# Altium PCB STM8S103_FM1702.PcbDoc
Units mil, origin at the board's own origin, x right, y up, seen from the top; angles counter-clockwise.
Board outline 2660.03 x 1670.03 mil, 2 copper layers (Top Layer, Bottom Layer); 63 components, 54 nets, 258 pads, 49 vias.
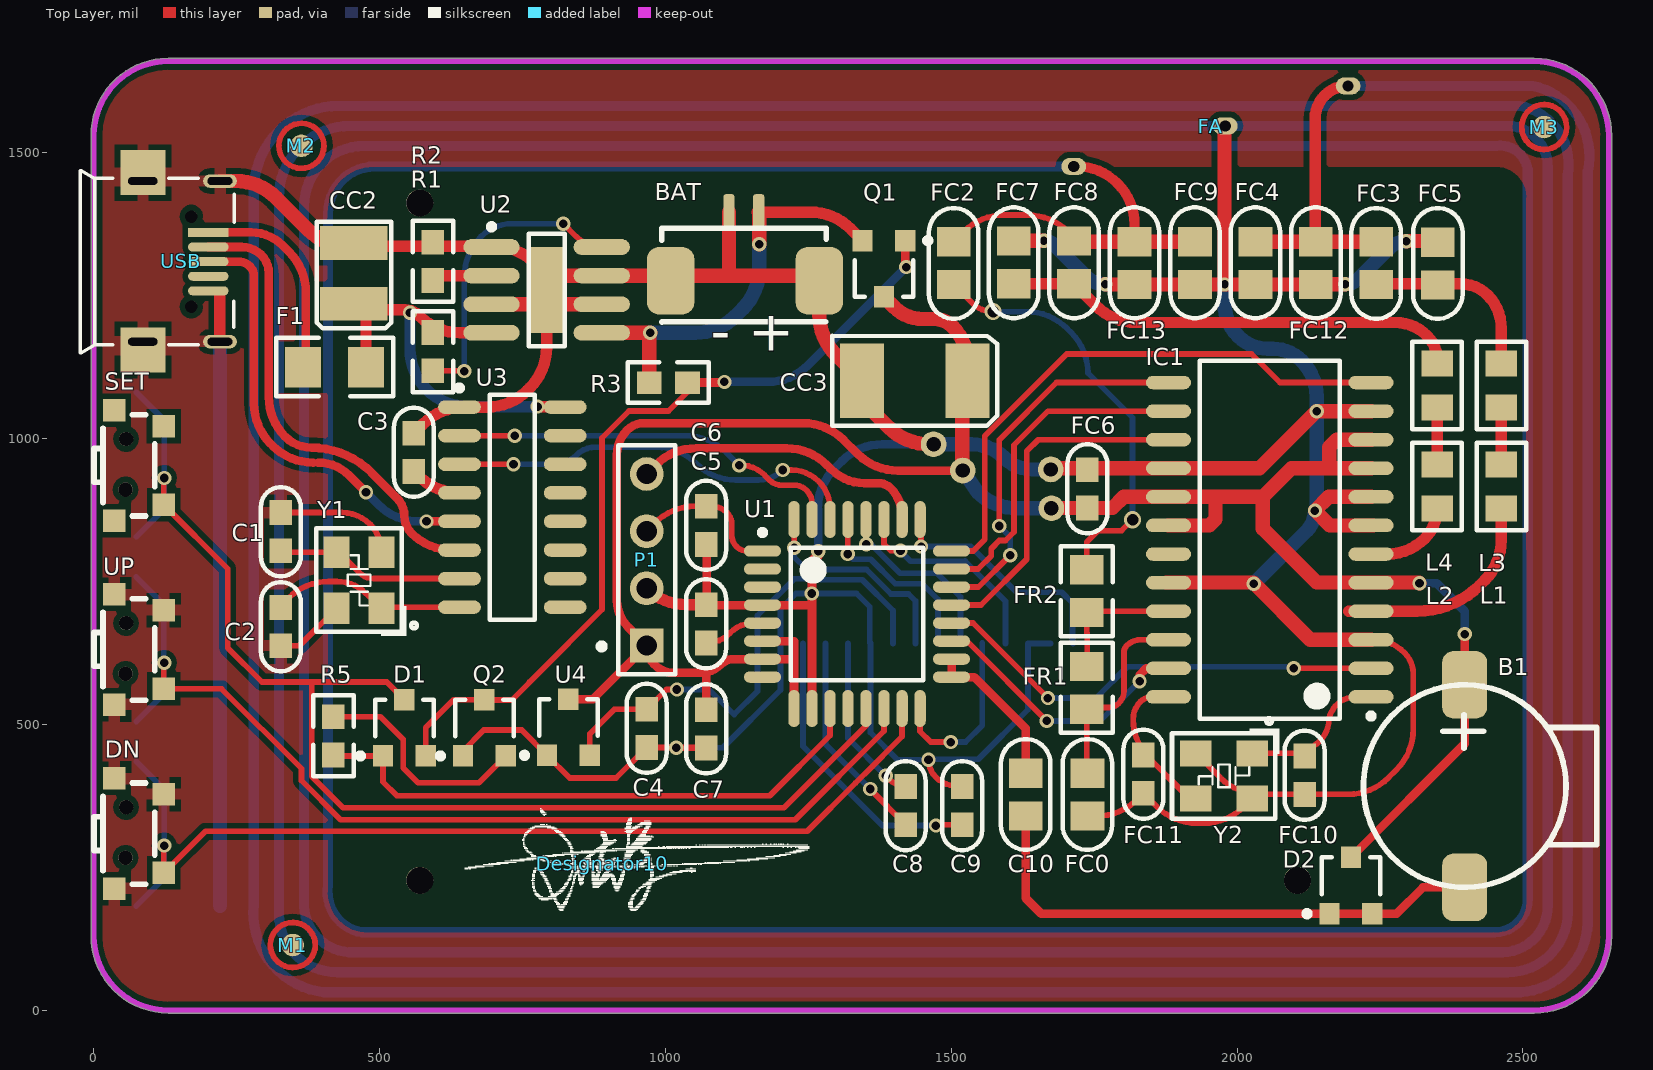
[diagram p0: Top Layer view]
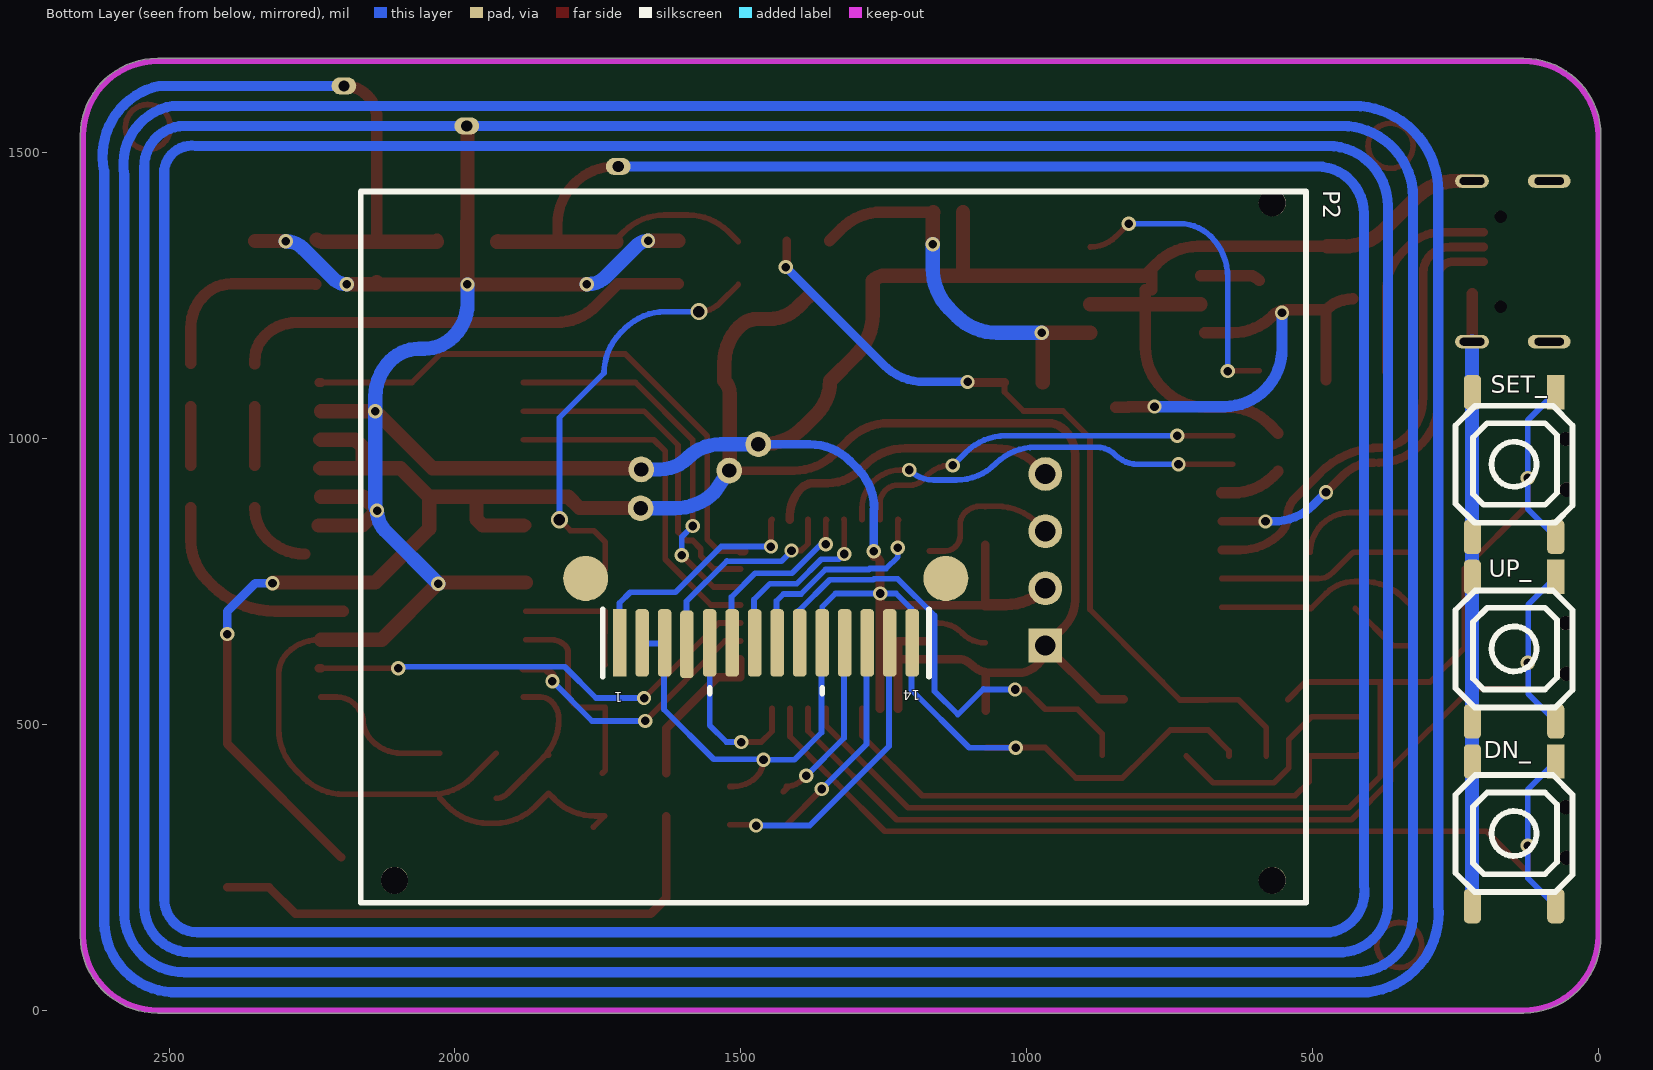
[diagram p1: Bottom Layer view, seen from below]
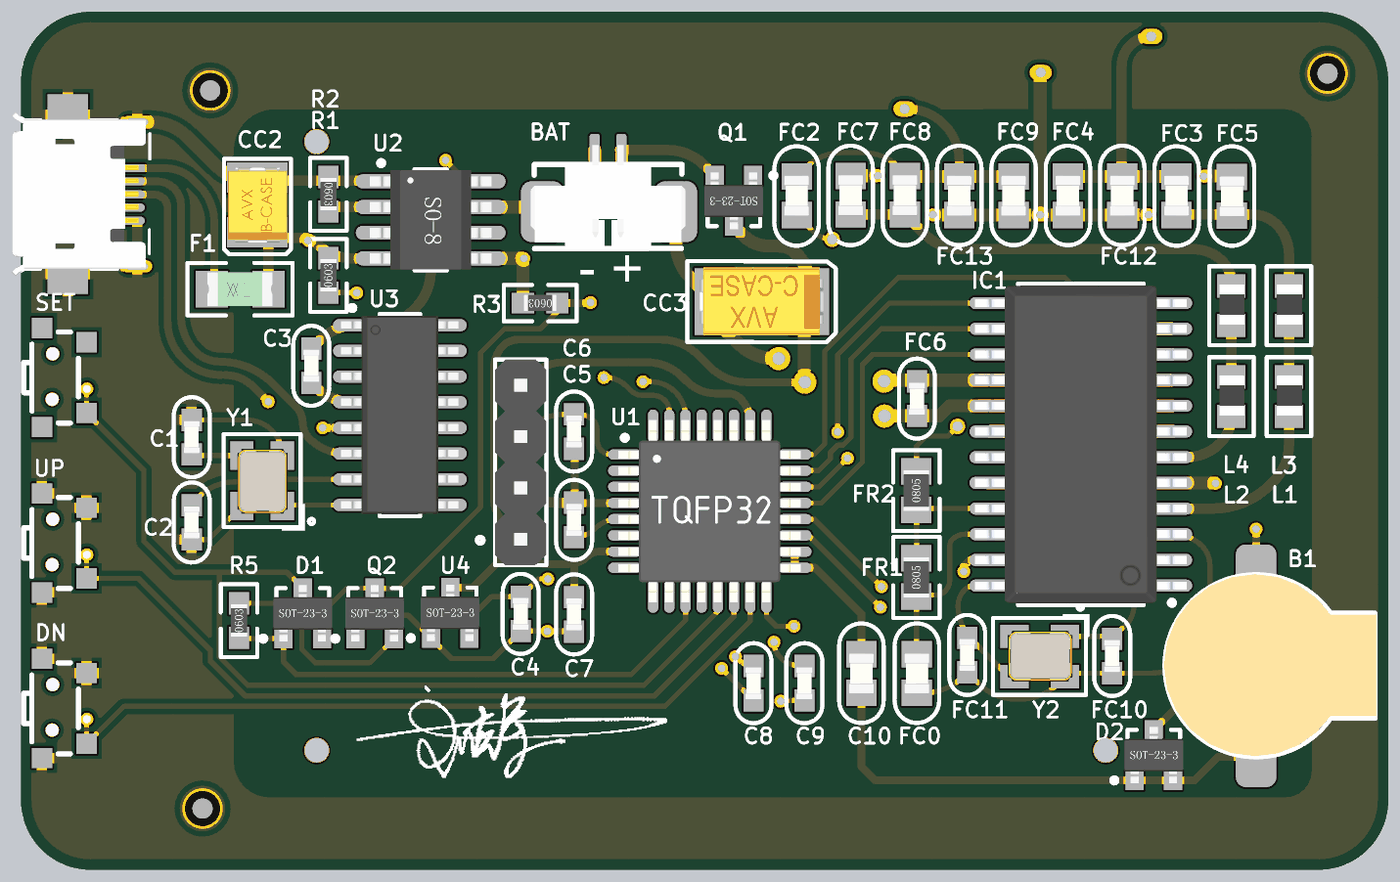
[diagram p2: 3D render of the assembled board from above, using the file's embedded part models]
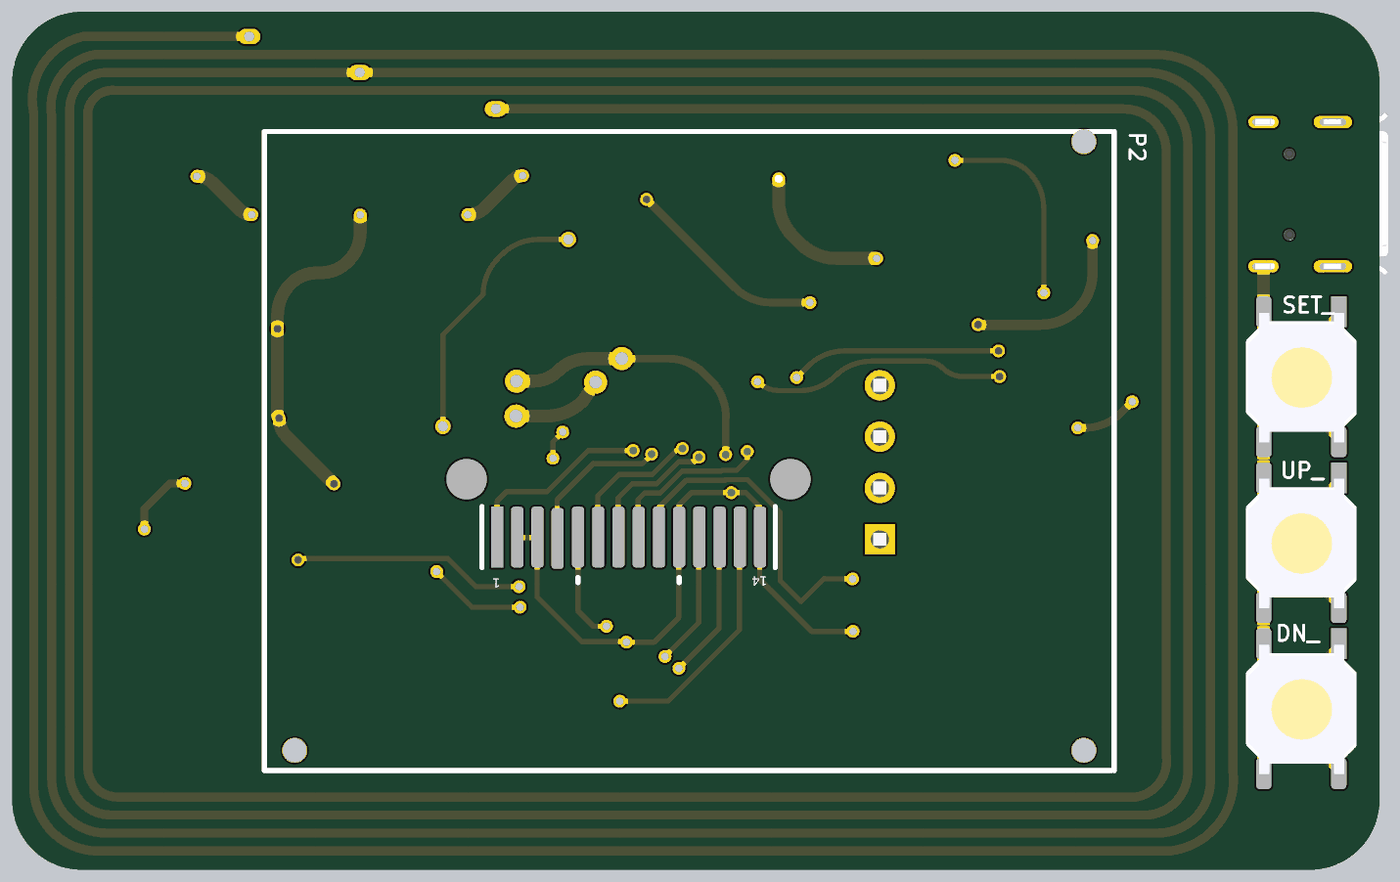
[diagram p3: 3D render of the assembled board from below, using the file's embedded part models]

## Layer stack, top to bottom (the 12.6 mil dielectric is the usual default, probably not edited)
Top Solder: solder mask 0.4, Solder Resist, Dk 3.5
Top Layer: signal copper 1.4
Dielectric1: dielectric 12.6, FR-4, Dk 4.8
Bottom Layer: signal copper 1.4
Bottom Solder: solder mask 0.4, Solder Resist, Dk 3.5

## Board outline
-4.45,117.69 cw(c0,120) -5.02,120 -5.02,1530 cw(c130,1530) 130,1665.02 2520,1665.02 cw(c2520,1530) 2655.02,1530 2655.02,130 cw(c2520,130) 2520,-5.01 130,-5.01 cw(c130,130)

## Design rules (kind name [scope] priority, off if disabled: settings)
Clearance poly [inpolygon] p1: gap=10
Clearance [All] p2: gap=8
ComponentClearance [All] p1: gap=0 collisioncheckmode=3 verticalgap=0 showdistances=FALSE
FabricationTestPointUsage TestPointUsage [All] p1: valid=0 allowmultiple=FALSE
FabricationTestpoint Testpoint [All] p1: side=3 testpointundercomponent=TRUE minsize=40 maxsize=100 preferedsize=60 minholesize=0 maxholesize=40 preferedholesize=32 testpointgrid=1 allowsidetop=TRUE allowsidebottom=TRUE usegrid=TRUE gridtolerance=0.01
HoleSize [All] p1: absolutevalues=TRUE maxlimit=150 minlimit=10 maxpercent=80.000 minpercent=20.000
PolygonConnect [All] p1: connectstyle=Relief reliefconductorwidth=20 reliefentries=4 polygonreliefangle="90 Angle" airgapwidth=10
RoutingVias [All] p1: holewidth=28 width=50 viastyle="Through Hole" minholewidth=28 minwidth=50 maxholewidth=28 maxwidth=50
SilkToSilkClearance [All] p1: silktosilkclearance=0
SolderMaskExpansion [All] p1: expansion=4
UnpouredPolygon [All] p1: allowunpoured=FALSE
Width [All] p1: maxlimit=50 minlimit=10 preferedwidth=20 bottomlayer_prefwidth=10 minimp=50.000000 maximp=50.000000 favimp=50.000000
24 further rules are at their usual default settings.

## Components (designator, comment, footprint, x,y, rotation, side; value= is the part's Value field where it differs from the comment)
B1 "BUZZER" BUZZ_9025 2398,392 r90 top
BAT "Battery" HX1.25-2 1289,1405 r180 top
C1 "C0603" C0603 327,837 r90 top
C2 "C0603" C0603 327,671 r270 top
C3 "C0603" C0603 559.57,976 r270 top
C4 "C0603" C0603 967,493 r270 top
C5 "C0603" C0603 1071,676 r90 top
C6 "C0603" C0603 1071,848 r270 top
C7 "C0603" C0603 1071,492 r270 top
C8 "C0603" C0603 1420,358 r90 top
C9 "C0603" C0603 1519,358 r90 top
C10 "C0805" C0805 1630,377 r90 top
CC2 "Cap Tan B" TAN-B-3528 455,1289 r270 top
CC3 "Cap Tan C" TAN-C-6032 1436,1101 r0 top
D1 "BAS40_5" SOT-23 543,494 r0 top
D2 "BAS40_5" SOT-23 2199,218 r0 top
Designator10 "Comment" LOGO 889,257 r0 top
DN "Button" BUTTON_SMD 79,309 r90 top
DN_ "Button" SWITCH_SMD 147,309 r270 bottom
F1 "300mA" F1206 421,1125 r0 top
FA "FM1702_Antenna" FM1702_ANTENNA 1834,1436 r180 top locked
FC0 "C0805" C0805 1738,377 r90 top
FC2 "C0805" C0805 1504,1307 r270 top
FC3 "C0805" C0805 2243.29,1307 r270 top
FC4 "C0805" C0805 2031.86,1307 r90 top
FC5 "C0805" C0805 2351,1306 r90 top
FC6 "C0603" C0603 1738,912 r90 top
FC7 "C0805" C0805 1609,1308 r270 top
FC8 "C0805" C0805 1714.71,1308 r270 top
FC9 "C0805" C0805 1926.14,1307 r90 top
FC10 "C0603" C0603 2118,411 r270 top
FC11 "C0603" C0603 1836,413 r270 top
FC12 "C0805" C0805 2137.57,1307 r90 top
FC13 "C0805" C0805 1820.43,1307 r90 top
FR1 "?" R0805 1737,564 r90 top
FR2 "?" R0805 1737,733 r90 top
IC1 "FM1702" SOP-24L 2057,823 r180 top
L1 "Inductor Chip" L2013-0805 2462,916 r90 top
L2 "Inductor Chip" L2013-0805 2350,916 r90 top
L3 "Inductor Chip" L2013-0805 2462,1093 r90 top
L4 "Inductor Chip" L2013-0805 2350,1093 r90 top
M1 "Mark" MARK 348,114 r180 top
M2 "Mark" MARK 363,1512 r180 top
M3 "Mark" MARK 2537,1545 r180 top
P1 "Header 4" HDR1X4 967,638 r90 top
P2 "SOG_12864" SOG12864 511,1432 r0 bottom
Q1 "IRLML6401" SOT-23 1382,1297 r180 top
Q2 "NPN-SMT" SO-G3/C2.5 683,494 r0 top
R1 "?" R0603 593,1152 r90 top
R2 "?" R0603 593,1310 r270 top
R3 "?" R0603 1005,1098 r180 top
R5 "?" R0603 419,480 r90 top
SET "Button" BUTTON_SMD 79,953 r90 top
SET_ "Button" SWITCH_SMD 147,955 r270 bottom
U1 "STM8S105KXT6C" TQFP-32AN 1335,693 r0 top
U2 "TP4056" SOP-8PAD 792,1260 r0 top
U3 "CH340G" SOP-16L 732,880 r0 top
U4 "XC6206_3.3V" SOT-23 830,495 r0 top
UP "Button" BUTTON_SMD 79,631 r90 top
UP_ "Button" SWITCH_SMD 147,632 r270 bottom
USB "USB" USB-B_Micro 153,1310 r0 top
Y1 "CRYSTAL" X3225 464,752 r90 top
Y2 "CRYSTAL" X3225 1977,410 r180 top

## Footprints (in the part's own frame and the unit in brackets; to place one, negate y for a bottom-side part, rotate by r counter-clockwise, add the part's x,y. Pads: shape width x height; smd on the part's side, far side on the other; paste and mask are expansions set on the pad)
BUTTON_SMD [mm]
  round 0.635 hole 0.635: 0(-1.075,0.6) 0(1.175,0.575)
  rect 1x1 smd: 1(-2.45,1.1) 1(1.75,-1.1) 1(2.45,1.1) 2(-1.75,-1.1)
  silkscreen extent -2.25,-0.7 2.25,2
BUZZ_9025 [mm]
  rrect50% 3x2 smd: 1(-4.5,0) 2(4.5,0)
  silkscreen extent -4.5,-5.87 4.5,4.5, body extent -4.47,-5.94 4.53,4.56, height 4
C0603 [mm]
  rect 1.1x1 smd: 1(-0.85,0) 2(0.85,0)
  silkscreen extent -1.98,-0.89 1.98,0.89, body extent -0.8,-0.4 0.8,0.4, height 0.3
C0805 [mm]
  rect 1.3x1.5 smd: 1(-0.95,0) 2(0.95,0)
  silkscreen extent -2.45,-1.1 2.47,1.1, body extent -1,-0.62 1,0.63, height 0.5
F1206 [mm]
  rect 1.6x1.8 smd: 1(-1.4,0) 2(1.4,0)
  silkscreen extent -2.6,-1.3 2.6,1.3, body extent -1.6,-0.83 1.6,0.83, height 0.56
FM1702_ANTENNA [mil]
  oval 43.31x30 hole 19.68: 1(-360,-180.94) 2(-145,-110.94) 3(120,-40)
  Bottom Layer lines w17.72: 120,-40 1342.11,-40 ccw(c1342.11,42.17) 1424.28,42.17 1424.28,1217.7 ccw(c1353.78,1229.2) 1365.28,1299.7 -616.32,1299.7 ccw(c-616.32,1241.7) -674.32,1241.7 -674.32,-34.3 ccw(c-625.99,-27.63) -619.32,-75.96 1361.15,-75.96 ccw(c1361.15,29.17) 1466.28,29.17 1466.28,1244.7 ccw(c1381.78,1250.2) 1387.28,1334.7 -629.72,1334.7 ccw(c-628.52,1253.9) -709.32,1252.7 -709.32,-38.14 ccw(c-637.94,-39.58) -639.39,-110.96 1385.27,-110.96 ccw(c1385.27,14.04) 1510.28,14.04 1510.28,1268.71 ccw(c1408.65,1268.07) 1408.02,1369.7 -638.72,1369.7 ; -360,-180.94 -683.39,-180.96 cw(c-657.02,-58.66) -779.32,-32.3 -779.32,1283.7 cw(c-654.02,1279.4) -649.73,1404.7 1431.28,1404.7 cw(c1415.74,1266.17) 1554.28,1250.64 1554.28,3.17 cw(c1405.15,3.17) 1405.15,-145.96 -660.06,-145.96 cw(c-641.86,-43.5) -744.32,-25.3 -744.32,1265.3 cw(c-639.32,1264.7) -638.73,1369.7
HDR1X4 [mm] "Connector; Header; 4 Position"
  rect 1.5x1.5 hole 0.9: 1(0,0)
  round 1.5 hole 0.9: 2(2.54,0) 3(5.08,0) 4(7.62,0)
  silkscreen extent -1.27,-1.27 8.89,2.14, body extent -1.27,-1.27 8.89,1.27, height 8.54
HX1.25-2 [mil] "53261(white colored)"
  rrect50% 82.68x118.11 smd: 0(20,129) 0(280,129)
  rrect50% 19.68x62.99 smd: 1(126,9) 2(178,9)
  silkscreen extent 8,37 295,201, body extent 1,0 303,204, height 138
L2013-0805 [mm]
  rect 1.15x1.4 smd: 1(-0.975,0) 2(0.975,0)
  silkscreen extent -1.95,-1.1 1.95,1.1, body extent -0.95,-0.65 1.05,0.6, height 0.5
LOGO [mil]
  silkscreen extent -240,-82 362,96
MARK [mm]
  round 1 smd mask+0.5: 1(0,0)
  Top Layer lines w0.254: 1,-0.018 ccw(c0,0) 1,-0.019
R0603 [mm]
  rect 1.1x1 smd: 1(-0.85,0) 2(0.85,0)
  silkscreen extent -1.8,-0.9 1.8,0.9, body extent -0.8,-0.4 0.8,0.4, height 0.45
R0805 [mm]
  rect 1.3x1.5 smd: 1(-0.95,0) 2(0.95,0)
  silkscreen extent -2,-1.15 2,1.15, body extent -1,-0.63 1,0.63, height 0.55
SO-G3/C2.5 [mm]
  rect 0.9x0.95 smd: 1(-0.95,-1.25) 2(0.95,-1.25) 3(0,1.25)
  silkscreen extent -2.07,-1.37 1.3,1.25, body extent -1.45,-1.4 1.45,1.4, height 1.2
SOG12864 [mm]
  round 1.2 hole 1.2: 0(1.5,0.5) 0(1.5,30.6) 0(40.5,30.6)
  round 2 smd: 0(16.002,17.19) 0(32.004,17.19)
  rect 0.6x3 smd: 1(30.5,20.054)
  rrect50% 0.6x3 smd: 2(29.5,20.054) 3(28.5,20.054) 4(27.508,20.117) 5(26.5,20.054) 6(25.5,20.054) 7(24.5,20.054) 8(23.5,20.054) 9(22.5,20.054) 10(21.5,20.054) 11(20.5,20.054) 12(19.5,20.054) 13(18.5,20.054) 14(17.5,20.054)
  silkscreen extent 0,0 42,31.6, body extent 0,0 42.01,31.6, height 2.6
SOP-8PAD [mm]
  oval 2.5x0.7 smd: 1(-2.45,1.905) 2(-2.45,0.635) 3(-2.45,-0.635) 4(-2.45,-1.905) 5(2.45,-1.905) 6(2.45,-0.635) 7(2.45,0.635) 8(2.45,1.905)
  rect 1.524x3.81 smd: 9(0,0)
  silkscreen extent -2.57,-2.5 0.8,2.93, body extent -3,-2.45 3,2.45, height 1.7
SOP-16L [mm] "SOIC, 16-Leads, Body 9.9x3.9mm, Pitch 1.27mm, IPC High Density"
  oval 1.9x0.6 smd: 1(-2.35,4.445) 2(-2.35,3.175) 3(-2.35,1.905) 4(-2.35,0.635) 5(-2.35,-0.635) 6(-2.35,-1.905) 7(-2.35,-3.175) 8(-2.35,-4.445) 9(2.35,-4.445) 10(2.35,-3.175) 11(2.35,-1.905) 12(2.35,-0.635) 13(2.35,0.635) 14(2.35,1.905) 15(2.35,3.175) 16(2.35,4.445)
  silkscreen extent -2.47,-5 1,5.42, body extent -2.91,-4.89 2.89,4.91, height 1.75
SOP-24L [mm] "SOIC, 24-Leads, Body 15.4x7.5mm, Pitch 1.27mm, IPC High Density"
  oval 2x0.6 smd: 1(-4.5,6.985) 2(-4.5,5.715) 3(-4.5,4.445) 4(-4.5,3.175) 5(-4.5,1.905) 6(-4.5,0.635) 7(-4.5,-0.635) 8(-4.5,-1.905) 9(-4.5,-3.175) 10(-4.5,-4.445) 11(-4.5,-5.715) 12(-4.5,-6.985) 13(4.5,-6.985) 14(4.5,-5.715) 15(4.5,-4.445) 16(4.5,-3.175) 17(4.5,-1.905) 18(4.5,-0.635) 19(4.5,0.635) 20(4.5,1.905) 21(4.5,3.175) 22(4.5,4.445) 23(4.5,5.715) 24(4.5,6.985)
  silkscreen extent -4.62,-7.95 3.1,7.96, body extent -5.23,-7.85 5.23,7.85, height 1.78
SOT-23 [mm]
  rect 0.9x0.95 smd: 1(-0.95,-1.25) 2(0.95,-1.25) 3(0,1.25)
  silkscreen extent -2.07,-1.37 1.3,1.25, body extent -1.45,-1.4 1.45,1.4, height 1.2
SWITCH_SMD [mil]
  rrect50% 60x30 smd: 1(-126,-73) 1(127,-73) 2(127,73)
  rect 60x30 smd: 2(-126,73)
  silkscreen extent -102,-102 102,102, body extent -124,-103 128,105, height 59
TAN-B-3528 [mm]
  rect 1.5x3 smd: 1(-1.35,0) 2(1.35,0)
  silkscreen extent -2.29,-1.65 2.44,1.65, body extent -1.85,-1.47 1.85,1.46, height 2.03
TAN-C-6032 [mm]
  rect 1.95x3.3 smd: 1(-2.35,0) 2(2.35,0)
  silkscreen extent -3.68,-2.01 3.66,2, body extent -3.05,-1.68 3.05,1.67, height 2.7
TQFP-32AN [mm] "Thin QFP, 32-Leads, Body 7x7mm, Pitch 0.8mm, IPC Medium Density"
  oval 1.65x0.508 smd: 1(-4.2,2.8) 2(-4.2,2) 3(-4.2,1.2) 4(-4.2,0.4) 5(-4.2,-0.4) 6(-4.2,-1.2) 7(-4.2,-2) 8(-4.2,-2.8) 17(4.2,-2.8) 18(4.2,-2) 19(4.2,-1.2) 20(4.2,-0.4) 21(4.2,0.4) 22(4.2,1.2) 23(4.2,2) 24(4.2,2.8)
  oval 0.508x1.65 smd: 9(-2.8,-4.2) 10(-2,-4.2) 11(-1.2,-4.2) 12(-0.4,-4.2) 13(0.4,-4.2) 14(1.2,-4.2) 15(2,-4.2) 16(2.8,-4.2) 25(2.8,4.2) 26(2,4.2) 27(1.2,4.2) 28(0.4,4.2) 29(-0.4,4.2) 30(-1.2,4.2) 31(-2,4.2) 32(-2.8,4.2)
  silkscreen extent -4.32,-2.95 2.95,3.75, body extent -4.52,-4.52 4.5,4.5, height 1.1
USB-B_Micro [mm]
  rect 1.8x0.4 smd: 1(1.198,1.287)
  oval 1.8x0.4 smd: 2(1.198,0.637) 3(1.198,-0.013) 4(1.198,-0.663) 5(1.198,-1.313)
  oval 1.9x0.6 hole 0.35 slot 1.3 at 0 deg: 6(-1.714,3.569) 7(-1.714,-3.569)
  rect 2x2 smd: 6(-1.702,3.937) 7(-1.702,-3.937)
  oval 1.5x0.6 hole 0.35 slot 1.1 at 0 deg: 6(1.714,3.569) 7(1.714,-3.569)
  round 0.5 hole 0.55 unplated: 8(0.445,1.987) 9(0.445,-2.013)
  silkscreen extent -4.49,-4.06 2.35,4.04, body extent -4.46,-4.03 2.16,4.05, height 2.7
X3225 [mm]
  rect 1.4x1.15 smd: 1(-1.25,-1) 2(1.25,-1) 3(1.25,1) 4(-1.25,1)
  silkscreen extent -2.46,-2.57 2.31,1.9, body extent -1.63,-1.27 1.57,1.23, height 0.6

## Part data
BAT: library part Battery-N, "Multicell Battery"
C1 C2 C3 C4 C5 C6 C7 C8 C9 C10 CC2 CC3 FC0 FC2 FC3 FC4 FC5 FC6 FC7 FC8 FC9 FC10 FC11 FC12 FC13: "Polarized Capacitor (Radial)"
D1 D2: "Default Diode"
F1: library part Fuse, "Fuse"
FR1 FR2: library part R0805
L1 L2 L3 L4: "Inductor"
P1: "Header, 4-Pin"
Q1: "P-Channel Power MOSFET"
Q2: "NPN Bipolar Transistor"
R1 R2 R3 R5: library part R0603
U1: library part STM8S105K4T6C, "ST 8-bit  Microcontroller"
U4: library part XC6206, "POSITIVE OUTPUT VOLTAGE"
Y1 Y2: "Crystal Oscillator"

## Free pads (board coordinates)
  round 45 hole 25: 0(1469,990) 0(1520,944) 0(1674,946) 0(1675,878)

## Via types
v1: diameter 25, hole 15, Top Layer to Bottom Layer, 47 vias
v2: diameter 30, hole 20, Top Layer to Bottom Layer, 2 vias

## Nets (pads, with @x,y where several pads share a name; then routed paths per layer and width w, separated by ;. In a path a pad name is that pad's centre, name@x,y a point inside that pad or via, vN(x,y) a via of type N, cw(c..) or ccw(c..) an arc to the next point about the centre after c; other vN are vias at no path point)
+3.3V: C4.1 P2.9 U4.2 | length 875.7
  Top Layer w10: U4.2 867.4,483.4 910.46,526.46 C4.1 1001.54,561 v1(1020,561)
  Bottom Layer w10: v1(1020,561) 1074,561 1075,562 1120,517 1161,558 1161,690.3 1225.2,754.5 1266.56,754.5 1268.06,753 1344,753 1397.83,699.17 P2.9@1397.83,641.48
+3.7V: BAT.1 Q1.2 R3.2 U2.5 | length 721.9
  Top Layer w20: BAT.1 1253.39,1396 cw(c1253.39,1296) 1324.1,1366.71 Q1.2
  Top Layer w25: U2.5 v1(973.06,1185) ccw(c976.74,1181.32) 971.54,1181.32 R3.2 ; BAT.1 cw(c1160.59,1393.59) 1164,1393.59 v1(1164,1340)
  Bottom Layer w25: v1(973.06,1185) 1051.58,1185 ccw(c1051.58,1285) 1122.29,1214.29 1134.71,1226.71 ccw(c1064,1297.42) 1164,1297.42 v1(1164,1340)
BEEP: C10.2 U1.17 U1.18 | length 276.9
  Top Layer w15: U1.18 U1.17 1540.24,582.76 1630,493 C10.2
CH_RX: U1.30 U3.3 | length 733.9
  Top Layer w10: U3.3 v1(734,955) ; v1(1205,945) 1219.72,945 cw(c1219.72,876.72) 1268,925 cw(c1220.31,877.31) 1287.76,877.31 U1.30
  Bottom Layer w10: v1(734,955) 805.37,955 ccw(c805.37,1009.63) 844,971 cw(c877.8,937.2) 877.8,985 983.99,985 cw(c983.99,885.99) 1054,956 ccw(c1122.81,1024.81) 1122.81,927.5 1162.75,927.5 ccw(c1162.75,987.25) 1186.17,932.28 ccw(c1162.75,987.25) v1(1205,945)
CH_TX: U1.31 U3.2 | length 692.3
  Top Layer w10: U3.2 v1(736,1005) ; v1(1129,953) 1129,954.07 cw(c1129,890.93) 1173.65,935.58 1182.05,927.17 ccw(c1202.99,948.12) 1202.99,918.5 1224.44,918.5 cw(c1224.44,886.62) 1234.52,916.86 cw(c1224.44,886.62) 1246.98,909.16 cw(c1224.58,886.76) 1252.92,900.93 cw(c1224.58,886.76) 1256.26,886.76 U1.31
  Bottom Layer w10: v1(736,1005) 1035.58,1005 cw(c1035.58,905) 1106.29,975.71 v1(1129,953)
CS: IC1.15 U1.21 | length 610
  Top Layer w10: U1.21 1551.81,708.75 1632,788.94 1632,978 1652,998 IC1.15
DN: DN.2 DN_.2 U1.15 | length 1781
  Top Layer w10: v1(123,288) 122.31,287.31 DN.2 195.2,313 1248,313 1332.5,397.5 1332.5,397.56 1347.44,412.5 1347.5,412.5 1413.74,478.74 U1.15
  Bottom Layer w10: DN_.2@74,182 123,231 v1(123,288) 123,386 DN_.2@74,435
GND: BAT.0 BAT.2 C1.2 C2.2 C3.1 C4.2 C5.2 C6.2 C7.2 C9.2 CC2.1 CC3.1 DN.1 DN_.1 FA.2 FC0.1 FC4.1 FC5.2 FC6.2 FC7.1 FC9.1 FC10.2 FC11.2 FC12.1 FC13.1 IC1.3 IC1.7 IC1.8 IC1.11 IC1.16 IC1.20 P1.2 P2.2 P2.3 P2.10 P2.14 pad.0@1469,990 pad.0@1674,946 Q2.1 R2.1 SET_.1 U1.4 U1.10 U2.1 U2.3 U2.6 U2.7 U2.9 U3.1 U4.1 UP.1 UP_.1 USB.5 USB.6 USB.7 Y1.2 Y1.4 Y2.2 Y2.4 | length 10849.4
  Top Layer w10: C1.2@324,870.46 434.12,870.46 cw(c434.12,801.21) Y1.2 ; C2.2 359.38,637.54 Y1.4 ; Q2.1 645.6,453.6 682,490 748.39,490 U4.1 832.39,406 913.46,406 C4.2 v1@1025.46,459.54 ; v1(1460,438) ccw(c1502.17,438) 1472.35,408.18 ccw(c1512.71,448.53) 1478.53,402.83 ccw(c1512.71,448.53) 1512.71,391.46 C9.2 ; FC0.1@1757.31,320.29 FC0.1 1754.64,339.6 ccw(c1754.64,439.6) 1825.35,368.89 FC11.2 1859.25,356.29 ccw(c1929.96,427) 1929.96,327 1941.16,327 ccw(c1941.16,427) 2011.87,356.29 Y2.4 ; Y2.2 1970.33,406.82 ccw(c2041.04,477.54) 2041.04,377.54 FC10.2 2194.11,377.54 ccw(c2194.11,477.54) 2264.82,406.82 2278.71,420.71 ccw(c2208,491.42) 2308,491.42 2308,588.79 ccw(c2256.79,588.79) 2293,625 ccw(c2237.47,569.47) 2237.47,648 IC1.3 ; FC12.1@2132.68,1274.49 FC12.1@2136.39,1278.2 ; v1@1025.46,459.54 1026.46,458.54 C7.2 1070,459.54 v1@1025.46,459.54
  Top Layer w15: USB.7@200.17,1171.51 ccw(c203.01,1171.51) USB.7@201,1169.5 ; C6.2@1072,814.54 1072,709.46 1072.72,708.75 U1.4 1256,708.75 ; v1(1256,729) 1256,782.71 cw(c1266.29,782.71) 1256.26,785.01 ; U1.10 1256.26,785.01 ; v1(1267,803) 1267,793.71 1266.29,793 ccw(c1266.29,782.71) 1256.26,785.01
  Top Layer w20: USB.7@201,1169.5 USB.7@220,1169.5 ; USB.7@220.5,1169.5 USB.5@220.5,1253 ; CC2.1@474,1336.15 700.43,1336.15 cw(c700.43,1236.15) 771.14,1306.86 U2.9@781,1297 ; C3.1@560,1009.46 576.25,1025.71 cw(c646.96,955) 646.96,1055 687.58,1055 ccw(c687.58,1155) 758.29,1084.29 762.71,1088.71 ccw(c692,1159.42) 792,1159.42 792,1235 U2.9 ; U2.9@781,1260 U2.9@781,1297 ; U2.9@793,1285 U2.9@781,1297 ; P1.2 ccw(c1035.89,806.89) 1035.89,709.46 C5.2 C5.2@1072,709.46
  Top Layer w25: USB.6@220.5,1450.5 248.08,1450.5 cw(c248.08,1350.5) 318.79,1421.21 374.56,1365.44 ccw(c445.27,1436.15) 445.27,1336.15 CC2.1@474,1336.15 ; U2.3 792,1235 U2.6 ; U2.9@793,1285 U2.7 1111,1285 ; BAT.2 1111,1285 ; pad.0@1469,990 1461.42,990 cw(c1461.42,1090) 1390.71,1019.29 1367.86,1042.14 cw(c1426.72,1101) CC3.1 1298.29,1146.19 cw(c1369,1216.9) 1269,1216.9 1269,1276 ccw(c1247.27,1254.27) 1247.27,1285 1111,1285 ; FC7.1 cw(c1610.45,1343.96) 1610.45,1346 v1(1662,1346) ; pad.0@1674,946 cw(c1678.83,941.17) 1678.83,948 IC1.16 2039,948 v1(2139,1048) IC1.11 ; v1(1769,1270) ccw(c1769.97,1270.97) 1769.97,1269.6 FC13.1 FC9.1 v1(1978,1269.6) ; IC1.20@1875.9,748 IC1.20 2028,748 2128,648 IC1.3 ; FA.2@1979,1546 1978,1545 1978,1379.48 1978.17,1379.31 1978.17,1269.77 v1(1978,1269.6) ; FC12.1@2136.39,1273.51 ccw(c2144.87,1281.99) 2144.87,1270 v1(2189,1270) ; FC12.1 FC4.1 v1(1978,1269.6) ; IC1.8 2160,898 v1(2136,874) 2162,848 IC1.7@2238.1,848 ; v1(2296,1345) cw(c2296.97,1344.03) 2296.97,1345.4 FC5.2@2349,1345.4
  Bottom Layer w10: v1(1019,459) 1100,459 1200.98,559.98 1200.98,701.98 1228,729 v1(1256,729) 1334,729 1357.46,705.54 P2.10 ; P2.10@1358.46,642.48 1358.46,485.54 1406,438 v1(1460,438) ; v1@1460,439 1547,439 1634.05,526.05 1634.05,641.48 P2.2@1673.42,641.48
  Bottom Layer w15: v1(1267,803) 1267,876.16 1266.29,876.87 cw(c1366.29,876.87) 1270,903.86 cw(c1366.29,876.87) 1295.58,947.58 1308.71,960.71 cw(c1379.42,890) 1379.42,990 pad.0@1469,990
  Bottom Layer w25: DN_.1@220.5,182.5 USB.7@220.5,1169.5 ; pad.0@1469,990 1535.06,990 cw(c1535.06,908.06) 1593,966 ccw(c1641.28,1014.28) 1641.28,946 pad.0@1674,946 ; v1(1662,1346) cw(c1662,1319.44) 1680.78,1338.22 1736,1283 ccw(c1767.38,1314.38) 1767.38,1270 v1(1769,1270) ; v1(1978,1269.6) 1978,1235.53 ccw(c2056.53,1235.53) 2001,1180 2002.79,1178.21 ccw(c2054,1229.43) 2054,1157 2062.3,1157 cw(c2062.3,1085.3) 2113,1136 cw(c2050.23,1073.23) 2139,1073.23 v1(2139,1048) 2139,881.24 cw(c2128.76,881.24) v1(2136,874) cw(c2085.3,874) 2121.15,838.15 v1(2029,746) ; v1(2189,1270) ccw(c2189,1303.8) 2212.9,1279.9 2265.27,1332.27 cw(c2296,1301.54) v1(2296,1345)
IRQ: IC1.2 U1.20 | length 816
  Top Layer w10: U1.20 1537.75,677.25 v1(1669,546) ; v1(2099,598) IC1.2
  Top Layer w15: IC1.2 IC1.2@2238.1,598
  Bottom Layer w10: v1(1669,546) 1753,546 1807.81,600.81 2096.19,600.81 v1(2099,598)
LCD_A0: P2.6 U1.28 | length 328.7
  Top Layer w10: U1.28 1350,857.61 1351,856.61 v1(1351,815)
  Bottom Layer w10: v1(1351,815) 1359.46,815 1410.22,764.23 1474.77,764.23 1515.94,723.06 P2.6@1515.94,641.48
LCD_CSB: P2.4 U1.27 | length 370.5
  Top Layer w10: U1.27 1382.24,815.76 1394,804 v1(1411,804)
  Bottom Layer w10: v1@1411,803 1428.5,785.5 1523.5,785.5 1524,786 1594.68,715.32 P2.4@1594.68,641.48
LCD_LEDA: P2.1 U1.25 | length 424.5
  Top Layer w10: U1.25 1447,856.59 v1(1447,811)
  Bottom Layer w10: v1(1447,811) 1534,811 1614,731 1693,731 1711.79,712.21 P2.1 ; P2.1@1712.79,641.48 P2.1@1712.79,642.48
LCD_POW: D1.1 R5.1 U1.11 | length 1015.9
  Top Layer w10: R5.1 420.75,444.79 D1.1 505.6,399.4 530,375 1182.34,375 1287.76,480.42 U1.11
LCD_RESET: P2.5 U1.16 | length 313
  Top Layer w10: U1.16 1445.24,487.76 1464,469 v1(1499,469)
  Bottom Layer w10: v1(1499,469) 1525,469 1554.31,498.31 P2.5
LCD_SCL: P2.7 U1.29 | length 327.9
  Top Layer w10: v1(1319,798) 1319,858.1 U1.29
  Bottom Layer w10: v1(1319,798) 1328,789 1358.91,789 1401.68,746.23 1448.77,746.23 1476.57,718.43 P2.7@1476.57,641.48
LCD_SDA: P2.8 U1.32 | length 384.7
  Top Layer w10: U1.32 1224,857.59 1225,856.59 v1(1225,809)
  Bottom Layer w10: v1(1225,809) 1225,793 1245.5,772.5 1274.02,772.5 1275.52,771 1351.46,771 1394.22,728.23 1425,728.23 1437.2,716.04 P2.8@1437.2,641.48
NetB1_1: B1.1 C10.1 D2.1 D2.2 | length 941.9
  Top Layer w15: C10.1 1630,196 1657.21,168.79 D2.1 2278.79,168.79 2324.83,214.83 B1.1
NetC1_1: C1.1 U3.7 Y1.3 | length 352.3
  Top Layer w10: C1.1@324,803.54 ccw(c329.61,809.14) 329.61,801.21 Y1.3 cw(c424.63,791.18) Y1.3@431.72,798.28 ; Y1.3@431.73,798.27 465,765 ccw(c489.14,789.14) 489.14,755 U3.7@658.48,755
NetC2_1: C2.1 U3.8 Y1.1 | length 366
  Top Layer w10: C2.1@324,704.46 340.25,720.71 cw(c410.96,650) 410.96,750 425,750 cw(c425,677.57) 476.21,728.79 501.39,703.61 ccw(c503.37,705.58) Y1.1 cw(c508.71,697.45) 508.71,705 U3.8@658.48,705
NetC3_2: C3.2 U3.4 | length 109.7
  Top Layer w20: C3.2@560,942.54 568.25,934.29 ccw(c638.96,1005) 638.96,905 U3.4@658.48,905
NetC8_1: C8.1 P2.12 | length 375.1
  Top Layer w10: v1(1358,387) 1358,386.54 C8.1
  Bottom Layer w10: P2.12@1279.72,641.48 1279.72,465.28 v1(1358,387)
NetC8_2: C8.2 P2.11 | length 317.7
  Top Layer w10: v1@1382,413 1391.89,403.11 ccw(c1420,431.21) C8.2@1415.77,391.69 ; C8.2 cw(c1420,431.21) C8.2@1415.77,391.69 ; C8.2@1425.46,382 C8.2@1415.77,391.69
  Bottom Layer w10: P2.11@1319.09,641.48 1319.09,475.91 v1(1385,410)
NetC9_1: C9.1 P2.13 | length 517.4
  Top Layer w10: v1@1473,317.81 v1(1473,323) ; v1@1476.71,324.54 C9.1
  Bottom Layer w10: P2.13@1240.35,641.48 1240.35,461.65 1379,323 v1(1473,323)
NetD1_2: D1.2 Q1.1 Q2.3 R3.1 | length 1547.8
  Top Layer w10: D1.2 580.4,494.4 629.21,543.21 Q2.3 683.43,542.79 731.4,542.79 829.83,641.21 830,641.21 ; 762.01,574.01 889,701 889,1000.99 936.04,1048.03 1005.16,1048.03 1038.46,1081.33 R3.1
  Top Layer w15: R3.1 1100.59,1098 ccw(c1100.59,1101.41) v1(1103,1099) ; Q1.1 1419.4,1303.86 ccw(c1424.86,1303.86) v1(1421,1300)
  Bottom Layer w15: v1(1103,1099) 1178.58,1099 ccw(c1178.58,1199) 1249.29,1128.29 v1(1421,1300)
NetF1_1: F1.1 USB.1 | length 369.5
  Top Layer w15: USB.1 275.24,1360.68 cw(c275.24,1283.24) 330,1338 341.59,1326.41 cw(c270.88,1255.7) 370.88,1255.7 F1.1@370.88,1117
NetFA_1: FA.1 FC3.1 FC4.2 FC12.2 | length 517.6
  Top Layer w20: FC4.2@2031.08,1348.32 FC4.2@2031.86,1348.32 ; FC12.2 cw(c2140.43,1347.26) 2136.39,1347.26 2136.39,1559.85 cw(c2193.21,1559.85) 2153.03,1600.03 cw(c2194,1559.06) FA.1@2194,1617
  Top Layer w25: FC4.2 FC12.2 2232.24,1344.4 ccw(c2232.24,1357.77) FC3.1@2241.69,1348.32
NetFA_3: FA.3 FC2.1 FC8.1 FC9.2 FC13.2 | length 644.5
  Top Layer w10: FC2.1 1521.31,1361.71 cw(c1592.02,1291) 1592.02,1391 1633.7,1391 cw(c1633.7,1291) 1704.41,1361.71 FC8.1@1714,1352.12
  Top Layer w17.72: FA.3 1719.58,1476 cw(c1719.58,1376) 1790.29,1446.71 1791.14,1445.86 cw(c1720.43,1375.15) 1820.43,1375.15 FC13.2 ; FC8.1 ccw(c1717.13,1347.82) FC8.1@1717.13,1344.4 ; FC9.2@1924.78,1349.32 FC9.2@1925.78,1348.32
  Top Layer w25: FC8.1@1717.13,1344.4 FC13.2 FC9.2
NetFC2_2: FC2.2 FR2.2 | length 746.3
  Top Layer w10: FC2.2 1536.47,1237.13 ccw(c1573,1273.67) v2(1573,1222) ; FR2.2 1737,819 1756.88,838.88 1797.88,838.88 v2(1817,858)
  Bottom Layer w10: v2(1573,1222) 1631.58,1222 cw(c1631.58,1122) 1702.29,1192.71 1709.71,1185.29 cw(c1639,1114.58) 1739,1114.58 1817,1036.58 v2(1817,858)
NetFC3_2: FC3.2 FC5.1 L3.2 | length 326.2
  Top Layer w20: FC3.2 cw(c2245.7,1267.18) 2245.7,1270.6 2349,1270.6 2390.69,1270.6 cw(c2390.69,1203.69) 2438,1251 cw(c2380.06,1193.06) 2462,1193.06 L3.2
NetFC7_2: FC7.2 FC8.2 L4.2 | length 807.3
  Top Layer w20: FC7.2 FC8.2 1753.02,1232.29 ccw(c1823.73,1303) 1823.73,1203 2276.47,1203 cw(c2276.47,1124.47) 2332,1180 cw(c2288.54,1136.54) 2350,1136.54 L4.2@2350,1130.4
NetFC10_1: FC10.1 IC1.1 Y2.1 | length 266
  Top Layer w10: Y2.1 2092.27,449.37 ccw(c2092.27,523.32) 2144.57,471.03 ccw(c2106.09,509.5) 2159.98,502 ; IC1.1 2206.38,548 ccw(c2206.38,503.62) 2175,535 2172.69,532.69 ccw(c2203.38,502) 2160.49,508.65 ; 2159.98,502 ccw(c2106.09,509.5) 2160.49,508.65 ; 2159.98,502 cw(c2203.38,502) 2160.49,508.65
NetFC11_1: FC11.1 IC1.24 Y2.3 | length 274.5
  Top Layer w10: FC11.1 FC11.1@1838.71,449.18 ; IC1.24 1850.31,548 ccw(c1850.31,520.69) 1831,540 ccw(c1862.38,508.62) 1818,508.62 ccw(c1913.64,508.62) FC11.1@1838.71,449.18 ; Y2.3 cw(c1927.79,398.19) 1908.3,378.7 1846.01,440.99 cw(c1913.64,508.62) FC11.1@1838.71,449.18
NetL1_2: L1.2 L3.1 | length 102.2
  Top Layer w20: L1.2@2462,953.4 L3.1@2462,1055.6
NetL2_2: L2.2 L4.1 | length 102.2
  Top Layer w20: L2.2@2350,953.4 L4.1@2350,1055.6
NetQ2_2: Q2.2 R5.2 | length 397.9
  Top Layer w10: R5.2 501.54,513.46 541,474 541,424 567,398 673.61,398 Q2.2
NetR1_1: R1.1 U2.8 | length 529.7
  Top Layer w10: R1.1 646.71,1118.54 cw(c646.71,1116.71) v1(648,1118) ; v1(821,1376) 843.29,1353.71 ccw(c888.46,1398.87) U2.8
  Bottom Layer w10: v1(648,1118) 648,1282.58 cw(c748,1282.58) 677.29,1353.29 cw(c732.12,1298.46) 732.12,1376 v1(821,1376)
NetR2_2: R2.2 U2.2 | length 105.2
  Top Layer w20: R2.2 cw(c613.44,1256.1) 600.18,1281.78 cw(c607.95,1274.01) 607.95,1285 U2.2
NetU3_5: U3.5 USB.3 | length 775.1
  Top Layer w15: USB.3 252.48,1309.5 cw(c252.48,1280.48) 273,1301 cw(c256.06,1284.06) 280.02,1284.06 280.02,1061.4 ccw(c380.02,1061.4) 309.31,990.69 ; 312.71,987.29 ccw(c383.42,1058) 383.42,958 ; 392.13,958 cw(c392.13,881.06) 446.54,935.46 v1(476,906) ; v1(581.83,855) U3.5@658.48,855
  Bottom Layer w15: v1(476,906) 497.71,884.29 ccw(c568.42,955) 568.42,855 v1(581.83,855)
NetU3_6: U3.6 USB.2 | length 835.2
  Top Layer w15: USB.2 258.98,1335.09 cw(c258.98,1286.98) 293,1321 cw(c261.62,1289.62) 306,1289.62 306,1073.01 ccw(c405.01,1073.01) 335,1003 ccw(c380.87,1048.87) 380.87,984 cw(c380.87,836.42) 485.23,940.77 530.25,895.75 cw(c499.49,864.98) 543,864.98 ccw(c586.4,864.98) 555.71,834.29 ccw(c626.42,905) 626.42,805 U3.6@658.48,805
NRST: C6.1 P1.3 U1.1 | length 268.2
  Top Layer w10: P1.3 981.18,852.18 cw(c1051.89,781.46) 1051.89,881.46 C6.1 ; C6.1@1072,881 1072,881.46 1081.01,881.46 cw(c1081.01,843.98) 1107.49,870.51 ; 1107.53,870.47 cw(c1087.03,850) 1116,850 1116,830.31 ccw(c1143.31,830.31) 1116.99,823.03 ccw(c1143.31,830.31) 1124,811 ccw(c1142.74,829.74) 1142.74,803.24 U1.1
RST: IC1.23 U1.19 | length 485.9
  Top Layer w10: U1.19 1527.24,645.76 v1(1667,506)
  Top Layer w15: v1(1829.31,575.31) 1829.31,586.31 1841,598 IC1.23
  Bottom Layer w10: v1(1667,506) 1760,506 v1(1829.31,575.31) v1@1833.31,575.31
RX: FR1.2 FR2.1 IC1.21 | length 232.9
  Top Layer w10: FR1.2@1737,604.4 1737.5,604.9 1737.5,659.6 1737,660.1 1737,698 IC1.21@1875.9,698
SCK: IC1.13 U1.22 | length 672.9
  Top Layer w10: U1.22 1547.24,740.24 v1(1603,796) ; v1(1584,847) 1584,998 1684,1098 IC1.13
  Bottom Layer w10: v1(1584,847) 1603,828 v1(1603,796)
SET: D1.3 SET.2 SET_.2 U1.13 | length 2230.7
  Top Layer w10: v1(123,931) 122.31,930.31 SET.2 234,772.41 234,634 294,574 381,574 ; D1.3 512.21,574 381,574 ; U1.13 1350.75,497.75 1207,354 436,354 381,409 381,574
  Bottom Layer w10: SET_.2@74,828 123,877 v1(123,931) 123,1032 SET_.2@74,1081
SI: IC1.14 U1.23 | length 590.3
  Top Layer w10: U1.23 1546.74,771.74 1569.73,794.73 1569.73,807.27 1583.96,821.5 1594.56,821.5 1609.5,836.44 1609.5,988.5 1669,1048 IC1.14
SO: IC1.12 U1.24 | length 1014.3
  Top Layer w10: U1.24 1538.24,803.24 1558.5,823.5 1558.5,1004.5 1702,1148 2025,1148 2075,1098 IC1.12
  Top Layer w15: U1.24@1493.35,803.24 U1.24 ; IC1.12 IC1.12@2238.1,1098
SWIM: P1.4 U1.26 | length 521.1
  Top Layer w15: P1.4 982.71,953.71 cw(c1053.42,883) 1053.42,983 1211.58,983 cw(c1211.58,883) 1282.29,953.71 1290,946 ccw(c1347.94,1003.94) 1347.94,922 1372.27,922 cw(c1372.27,891.27) 1394,913 cw(c1346.34,865.34) 1413.74,865.34 U1.26
TX1: IC1.4 L1.1 | length 387.9
  Top Layer w20: IC1.4@2195.1,698 2314.36,698 ccw(c2314.36,854.07) 2424.71,743.71 2432.71,751.71 ccw(c2362,822.42) 2462,822.42 L1.1@2462,878.6
TX2: IC1.6 L2.1 | length 131.9
  Top Layer w20: IC1.6@2262.82,798 ccw(c2262.82,890.18) 2328,825 ccw(c2274.89,878.11) 2350,878.11 L2.1@2350,878.6
UP: U1.14 UP.2 UP_.2 | length 1809.1
  Top Layer w10: v1@122.31,607.31 UP.2 223.44,562.1 363,422.54 363,401.54 431.54,333 1227,333 1382.24,488.24 U1.14
  Bottom Layer w10: UP_.2@74,505 122.31,553.31 122.31,709.69 UP_.2@74,758
  other v1: 123,608
VCAP: C5.1 U1.5 | length 107
  Top Layer w10: C5.1@1072,642.54 ccw(c1072,699.36) 1112.18,659.18 1113,660 cw(c1154.65,618.35) 1154.65,677.25 U1.5
VCC: CC2.2 F1.2 R1.2 U2.4 U3.16 | length 809.7
  Top Layer w20: CC2.2@428.89,1244.54 cw(c428.89,1177.91) CC2.2@476,1225.02 ; F1.2@476,1103.12 CC2.2@476,1225.02 ; U2.4@688.48,1185 640.42,1185 cw(c640.42,1285) 569.71,1214.29 ccw(c543.8,1188.38) 543.8,1225.02 CC2.2@476,1225.02 ; v1(776,1056) 821.33,1056 822.33,1055.01 ccw(c823.42,1155) U3.16@822.88,1055 ; U3.16@843.52,1055 U3.16@823.42,1055 ; U3.16@822.88,1055 ccw(c823.42,1155) U3.16@823.42,1055 ; U3.16@822.88,1055 U3.16@823.42,1055
  Bottom Layer w20: v1(553,1220) 553,1156.42 ccw(c653,1156.42) 582.29,1085.71 582.71,1085.29 ccw(c653.42,1156) 653.42,1056 v1(776,1056)
VDD: B1.2 C7.1 CC3.2 D2.3 FC6.1 IC1.5 IC1.9 IC1.10 IC1.17 IC1.18 P1.1 pad.0@1520,944 pad.0@1675,878 Q1.3 U1.6 U1.7 U1.9 U4.3 | length 4120.1
  Top Layer w15: U4.3 873.21,544.21 P1.1 ; C7.1@1071,524 1071,588.73 ; U1.6 1224.76,645.76 1224.76,614.26 ; U1.9 1224.76,614.26 ; pad.0@1519,950 cw(c1504.51,964.49) 1504.51,944 1406.42,944 cw(c1406.42,1044) 1360.55,955.14 cw(c1406.42,1044) 1335.71,973.29 1311.29,997.71 ccw(c1240.58,927) 1240.58,1027 961.97,1027 ccw(c961.97,986.03) 933,1015 ccw(c976.46,971.54) 915,971.54 915,717 ccw(c980.18,717) 934.09,670.91 P1.1 ; D2.3 2398,466.21 B1.2 v1(2398,658) ; P1.1 ccw(c1015,638) 1015,590 1060.79,590 ccw(c1060.79,641.21) 1097,605 cw(c1119.36,582.64) 1119.36,614.26 U1.7 1224.76,614.26
  Top Layer w20: IC1.18@1875.9,848 IC1.18 ; IC1.9 IC1.9@2238.1,948 ; IC1.10 IC1.10@2238.1,998
  Top Layer w25: Q1.3 1400.13,1229.66 ccw(c1450,1279.53) 1450,1209 1470.62,1209 cw(c1470.62,1164.62) 1502,1196 cw(c1437.98,1131.98) 1528.52,1131.98 CC3.2 ccw(c1551.5,1078.02) 1519,1078.02 pad.0@1519,950 ; pad.0@1675,878 cw(c1676.29,876.71) 1676.29,878.54 FC6.1 1782,878.54 1801.46,898 IC1.17 1962,898 ; IC1.18 1951,848 1962,859 1962,898 ; IC1.9 2161,948 ; IC1.10 2174,998 2161,985 2161,948 ; v1(2319,747) 2318,748 IC1.5 2139,748 2045,842 2045,898 ; 1962,898 2045,898 ; 2045,898 2095,948 2161,948
  Bottom Layer w15: v1(2319,747) 2349,747 2398,698 v1(2398,658)
  Bottom Layer w25: pad.0@1520,944 1544.71,907.29 ccw(c1615.42,978) 1615.42,878 pad.0@1675,878
VMID: FC0.2 FR1.1 IC1.22 | length 351.6
  Top Layer w10: FC0.2@1742,414.4 1737,419.4 1737,529.6 1775.13,529.6 ccw(c1775.13,554.87) 1793,537 ccw(c1771.27,558.73) 1802,558.73 1802,625.93 cw(c1819.07,625.93) 1807,638 cw(c1831.14,613.86) 1831.14,648 IC1.22@1875.9,648
pads on no net: DN.0 IC1.19 M1.1 M2.1 M3.1 P2.0 SET.0 SET.1 U1.2 U1.3 U1.8 U1.12 U3.9 U3.10 U3.11 U3.12 U3.13 U3.14 U3.15 UP.0 USB.4 USB.8 USB.9

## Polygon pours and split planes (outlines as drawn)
GND on Top Layer "Top Layer-No Net" (solid, pour order 9): 130,1660 100,1660 ccw(c100,1560) 0,1560 0,1530 0,100 ccw(c100,100) 100,0 141,0 2550,0 ccw(c2550,100) 2650,100 2650,219 2650,1560 ccw(c2550,1560) 2550,1660 2494,1660

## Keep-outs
Keep-Out Layer:
  lines w10: 0,120 0,1530 cw(c130,1530) 130,1660 2520,1660 cw(c2520,1530) 2650,1530 2650,130 cw(c2520,130) 2520,0 130,0 cw(c130,130) 0,130

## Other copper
Top Layer:
  pour cut-out: 1985,1562 cw(c1985,1546) 2001,1546 cw(c1987,1546) 1987,1532 1972,1532 cw(c1972,1547) 1957,1547 cw(c1972,1547) 1972,1562
  pour cut-out: 2453,1475 cw(c2453,1422) 2506,1422 2506,187.9 cw(c2454,188) 2454,136 479,136 cw(c479,206) 409,206 409,1395 cw(c489,1395) 489,1475

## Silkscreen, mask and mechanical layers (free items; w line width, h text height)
Top Overlay:
  text "- +" at 1079,1130 h120
Mechanical 16:
  drawing of 1873 lines, arcs and shapes, not listed
  text "1" at -2479,4265 h70
  text "2" at 381,4265 h70
  text "3" at 3261,4265 h70
  text "4" at 6131,4265 h70
  text "A" at -3831,3359 h70
  text "A" at 7469,3359 h70
  text "B" at -3831,1467 h70
  text "B" at 7469,1467 h70
  text "C" at -3831,-443 h70
  text "ENGINEER:" at 2944,-1900 h45
  text "TITLE:" at 4444,-1900 h45
  text "PCB DESIGNER:" at 2944,-2195 h45
  text "D" at -3831,-2333 h70
  text "D" at 7469,-2333 h70
  text "DATE:" at 2944,-2500 h45
  text "PART NO.:" at 4444,-2500 h45
  text "REV:" at 6544,-2500 h45
  text "Altium Limited" at 1644,-2600 h70
  text ".PRINT_DATE" at 2994,-2620 h70
  text "12a Rodborough Rd" at 1644,-2700 h70
  text "Frenchs Forest" at 1644,-2800 h70
  text "FILE NAME:" at 2944,-2800 h45
  text "DWG NO:" at 4444,-2800 h45
  text "SCALE:" at 6544,-2800 h45
  text "NSW 2086" at 1644,-2900 h70
  text ".PCB_FILE_NAME_NO_PATH" at 2994,-2920 h70
  text "1" at -2479,-3135 h70
  text "2" at 381,-3135 h70
  text "3" at 3261,-3135 h70
  text "4" at 6131,-3135 h70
